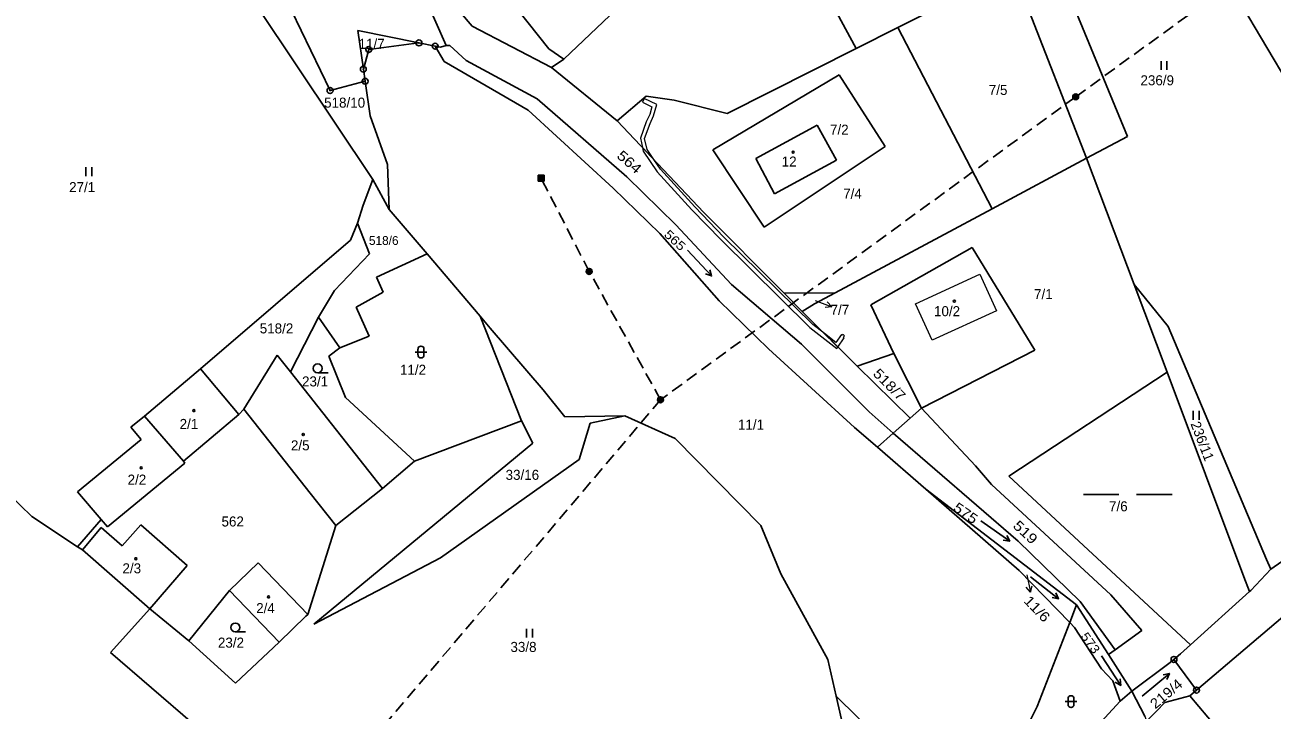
# Model space of a CAD drawing. Extents: x -885985 to -883535, y -1030025 to -1027941.
# Drawn here: x -884740.1 to -884528.7, y -1028559.6 to -1028443.4 of the extents above; entities that cross this region are included whole.
import ezdxf
from ezdxf.enums import TextEntityAlignment as Align

# ---------------------------------------------------------------- set-up
doc = ezdxf.new("R2010")
doc.units = 0
doc.header["$LTSCALE"] = 0.68
doc.linetypes.add('MEDIUM_DASHED', pattern=[4.5, 3, -1.5])
for name, color, linetype, lineweight in [('1', 7, 'Continuous', 25), ('13', 7, 'Continuous', 13), ('3', 7, 'Continuous', 25), ('4', 7, 'Continuous', 13), ('5', 7, 'Continuous', 25), ('6', 7, 'Continuous', 25), ('7', 7, 'Continuous', 13), ('8', 7, 'Continuous', 25)]:
    doc.layers.add(name, color=color, linetype=linetype, lineweight=lineweight)
doc.layers.add('2', color=7, linetype='Continuous')

msp = doc.modelspace()

# ---------------------------------------------------------------- linework, layer by layer
at = {"layer": '1'}
for p, q in [((-884556.32, -1028401.83), (-884531.74, -1028443.62)), ((-884575.21, -1028409.11), (-884553.2, -1028462.33)), ((-884610.56, -1028426.3), (-884599.2, -1028447.46)), ((-884662.42, -1028433.46), (-884651.31, -1028447.47)), ((-884592.12, -1028443.9), (-884572.61, -1028434.07)), ((-884572.61, -1028434.07), (-884560.14, -1028466.04)), ((-884636.88, -1028437.92), (-884648.77, -1028449.22)), ((-884681.12, -1028469.67), (-884700.53, -1028440.64)), ((-884668.71, -1028446.95), (-884672.22, -1028438.93)), ((-884694.93, -1028441.01), (-884688.38, -1028454.57)), ((-884666.24, -1028441.34), (-884664.31, -1028443.64)), ((-884664.31, -1028443.64), (-884650.86, -1028450.66)), ((-884599.2, -1028447.46), (-884592.12, -1028443.9)), ((-884576.15, -1028474.62), (-884592.12, -1028443.9)), ((-884531.74, -1028443.62), (-884517.46, -1028467.79)), ((-884681.82, -1028447.6), (-884673.31, -1028446.49)), ((-884673.31, -1028446.49), (-884670.55, -1028447.05)), ((-884670.55, -1028447.05), (-884669.01, -1028449.65)), ((-884670.55, -1028447.05), (-884669.68, -1028447.22)), ((-884669.68, -1028447.22), (-884668.71, -1028446.95)), ((-884668.71, -1028446.95), (-884668.09, -1028446.91)), ((-884668.09, -1028446.91), (-884665.31, -1028449.46)), ((-884682.73, -1028450.95), (-884681.82, -1028447.6)), ((-884651.31, -1028447.47), (-884648.77, -1028449.22)), ((-884650.86, -1028450.66), (-884648.77, -1028449.22)), ((-884599.2, -1028447.46), (-884621.05, -1028458.46)), ((-884682.44, -1028452.99), (-884682.73, -1028450.95)), ((-884669.01, -1028449.65), (-884654.78, -1028457.91)), ((-884665.31, -1028449.46), (-884653.27, -1028455.95)), ((-884650.86, -1028450.66), (-884639.69, -1028459.71)), ((-884688.38, -1028454.57), (-884682.44, -1028452.99)), ((-884682.44, -1028452.99), (-884681.6, -1028458.88)), ((-884623.49, -1028464.59), (-884602.1, -1028451.92)), ((-884602.1, -1028451.92), (-884594.29, -1028464.04)), ((-884639.69, -1028459.71), (-884634.82, -1028455.53)), ((-884634.82, -1028455.53), (-884630.02, -1028456.22)), ((-884653.27, -1028455.95), (-884638.05, -1028469.2)), ((-884630.02, -1028456.22), (-884621.05, -1028458.46)), ((-884681.6, -1028458.88), (-884678.63, -1028467.13)), ((-884654.78, -1028457.91), (-884640.39, -1028471.1)), ((-884639.69, -1028459.71), (-884625, -1028475.22)), ((-884616.21, -1028466.09), (-884605.79, -1028460.43)), ((-884605.79, -1028460.43), (-884602.55, -1028466.35)), ((-884553.2, -1028462.33), (-884560.14, -1028466.04)), ((-884614.8, -1028477.73), (-884623.49, -1028464.59)), ((-884613.03, -1028472.1), (-884616.21, -1028466.09)), ((-884594.29, -1028464.04), (-884614.8, -1028477.73)), ((-884576.15, -1028474.62), (-884560.14, -1028466.04)), ((-884560.14, -1028466.04), (-884552.09, -1028487.46)), ((-884678.63, -1028467.13), (-884678.35, -1028474.71)), ((-884602.55, -1028466.35), (-884613.03, -1028472.1)), ((-884682.77, -1028474.02), (-884681.12, -1028469.67)), ((-884678.35, -1028474.71), (-884681.12, -1028469.67)), ((-884638.05, -1028469.2), (-884629.79, -1028477.34)), ((-884640.39, -1028471.1), (-884632.48, -1028478.81)), ((-884683.74, -1028477.05), (-884682.77, -1028474.02)), ((-884671.9, -1028482.28), (-884678.35, -1028474.71)), ((-884625, -1028475.22), (-884611.42, -1028488.93)), ((-884602.78, -1028488.87), (-884576.15, -1028474.62)), ((-884684.94, -1028479.93), (-884683.74, -1028477.05)), ((-884683.74, -1028477.05), (-884681.72, -1028482.27)), ((-884632.48, -1028478.81), (-884622.39, -1028490.2)), ((-884629.79, -1028477.34), (-884620.32, -1028487.43)), ((-884710.34, -1028501.74), (-884684.94, -1028479.93)), ((-884681.72, -1028482.27), (-884687.65, -1028488.49)), ((-884680.49, -1028486.21), (-884671.9, -1028482.28)), ((-884662.93, -1028492.81), (-884671.9, -1028482.28)), ((-884596.68, -1028490.88), (-884579.51, -1028481.17)), ((-884579.51, -1028481.17), (-884568.93, -1028498.58)), ((-884679.38, -1028488.73), (-884680.49, -1028486.21)), ((-884687.65, -1028488.49), (-884690.33, -1028492.98)), ((-884683.95, -1028491.32), (-884679.38, -1028488.73)), ((-884620.32, -1028487.43), (-884608.48, -1028497.57)), ((-884611.42, -1028488.93), (-884602.78, -1028488.87)), ((-884611.42, -1028488.93), (-884608.37, -1028492.02)), ((-884606.23, -1028490.72), (-884602.78, -1028488.87)), ((-884546.3, -1028494.59), (-884552.09, -1028487.46)), ((-884546.5, -1028502.34), (-884552.09, -1028487.46)), ((-884681.75, -1028496.21), (-884683.95, -1028491.32)), ((-884622.39, -1028490.2), (-884614.07, -1028498.38)), ((-884608.37, -1028492.02), (-884606.23, -1028490.72)), ((-884592.83, -1028499.15), (-884596.68, -1028490.88)), ((-884690.33, -1028492.98), (-884695.09, -1028502.26)), ((-884690.33, -1028492.98), (-884686.71, -1028498.18)), ((-884608.37, -1028492.02), (-884599.03, -1028501.29)), ((-884773, -1028493.92), (-884738.95, -1028526.77)), ((-884661.22, -1028494.85), (-884652.28, -1028505.29)), ((-884529.63, -1028534.07), (-884546.3, -1028494.59)), ((-884686.71, -1028498.18), (-884681.75, -1028496.21)), ((-884608.48, -1028497.57), (-884597.01, -1028509.07)), ((-884697.32, -1028499.43), (-884703.01, -1028508.61)), ((-884695.09, -1028502.26), (-884697.32, -1028499.43)), ((-884688.6, -1028499.59), (-884686.71, -1028498.18)), ((-884685.76, -1028506.6), (-884688.6, -1028499.59)), ((-884614.07, -1028498.38), (-884599.45, -1028511.68)), ((-884599.03, -1028501.29), (-884592.83, -1028499.15)), ((-884592.83, -1028499.15), (-884588.11, -1028508.4)), ((-884568.93, -1028498.58), (-884588.11, -1028508.4)), ((-884710.34, -1028501.74), (-884719.81, -1028509.75)), ((-884703.83, -1028509.49), (-884710.34, -1028501.74)), ((-884599.03, -1028501.29), (-884590.06, -1028510.09)), ((-884679.5, -1028522.02), (-884695.09, -1028502.26)), ((-884573.29, -1028519.93), (-884546.5, -1028502.34)), ((-884533.47, -1028537), (-884546.5, -1028502.34)), ((-884652.28, -1028505.29), (-884648.6, -1028509.88)), ((-884674.08, -1028517.38), (-884685.76, -1028506.6)), ((-884590.06, -1028510.09), (-884588.11, -1028508.4)), ((-884588.11, -1028508.4), (-884578.97, -1028518.18)), ((-884719.81, -1028509.75), (-884722.14, -1028511.67)), ((-884713.22, -1028517.42), (-884719.81, -1028509.75)), ((-884713.22, -1028517.42), (-884703.83, -1028509.49)), ((-884703.83, -1028509.49), (-884703.01, -1028508.61)), ((-884703.01, -1028508.61), (-884691.74, -1028522.82)), ((-884648.6, -1028509.88), (-884638.43, -1028509.73)), ((-884638.43, -1028509.73), (-884644.27, -1028510.97)), ((-884629.87, -1028513.55), (-884638.43, -1028509.73)), ((-884597.01, -1028509.07), (-884592.91, -1028512.64)), ((-884592.91, -1028512.64), (-884590.06, -1028510.09)), ((-884722.14, -1028511.67), (-884720.38, -1028513.76)), ((-884674.08, -1028517.38), (-884655.95, -1028510.57)), ((-884653.99, -1028514.34), (-884655.95, -1028510.57)), ((-884644.27, -1028510.97), (-884646.15, -1028517.1)), ((-884599.45, -1028511.68), (-884595.59, -1028515.05)), ((-884592.91, -1028512.64), (-884595.59, -1028515.05)), ((-884592.91, -1028512.64), (-884571.73, -1028530.95)), ((-884720.38, -1028513.76), (-884731.22, -1028522.6)), ((-884691.12, -1028545.04), (-884653.99, -1028514.34)), ((-884615.36, -1028528.29), (-884629.87, -1028513.55)), ((-884595.59, -1028515.05), (-884587.41, -1028522.17)), ((-884726.13, -1028528.55), (-884712.97, -1028517.76)), ((-884712.97, -1028517.76), (-884713.22, -1028517.42)), ((-884679.5, -1028522.02), (-884674.08, -1028517.38)), ((-884646.15, -1028517.1), (-884669.65, -1028533.81)), ((-884578.97, -1028518.18), (-884576.28, -1028521.36)), ((-884544.9, -1028546.32), (-884573.29, -1028519.93)), ((-884731.22, -1028522.6), (-884727.19, -1028527.32)), ((-884691.74, -1028522.82), (-884687.39, -1028528.3)), ((-884687.39, -1028528.3), (-884679.5, -1028522.02)), ((-884587.41, -1028522.17), (-884571.59, -1028535.96)), ((-884587.41, -1028522.17), (-884561.86, -1028541.74)), ((-884576.28, -1028521.36), (-884556.05, -1028540.05)), ((-884738.95, -1028526.77), (-884731.18, -1028531.92)), ((-884727.19, -1028527.32), (-884731.18, -1028531.92)), ((-884727.19, -1028527.32), (-884726.13, -1028528.55)), ((-884727.2, -1028528.67), (-884730.37, -1028532.45)), ((-884723.61, -1028531.77), (-884727.2, -1028528.67)), ((-884720.48, -1028528.2), (-884723.61, -1028531.77)), ((-884712.6, -1028535.1), (-884720.48, -1028528.2)), ((-884692.17, -1028543.38), (-884687.39, -1028528.3)), ((-884611.99, -1028536.52), (-884615.36, -1028528.29)), ((-884571.73, -1028530.95), (-884561.2, -1028541.18)), ((-884528.9, -1028535.72), (-884521.21, -1028530.3)), ((-884731.18, -1028531.92), (-884730.37, -1028532.45)), ((-884730.37, -1028532.45), (-884718.91, -1028542.44)), ((-884712.6, -1028535.1), (-884718.91, -1028542.44)), ((-884700.56, -1028534.64), (-884705.42, -1028539.35)), ((-884692.17, -1028543.38), (-884700.56, -1028534.64)), ((-884669.65, -1028533.81), (-884691.12, -1028545.04)), ((-884532.3, -1028539.31), (-884528.9, -1028535.72)), ((-884528.9, -1028535.72), (-884529.63, -1028534.07)), ((-884603.97, -1028551.04), (-884611.99, -1028536.52)), ((-884571.59, -1028535.96), (-884562.97, -1028544.77)), ((-884532.53, -1028539.51), (-884533.47, -1028537)), ((-884705.42, -1028539.35), (-884712.34, -1028547.85)), ((-884697.02, -1028548.08), (-884705.42, -1028539.35)), ((-884556.05, -1028540.05), (-884550.74, -1028546.11)), ((-884542.49, -1028548.55), (-884532.53, -1028539.51)), ((-884541.49, -1028556.22), (-884520.3, -1028538.19)), ((-884532.53, -1028539.51), (-884532.3, -1028539.31)), ((-884561.86, -1028541.74), (-884562.97, -1028544.77)), ((-884561.86, -1028541.74), (-884556.4, -1028550.2)), ((-884561.2, -1028541.18), (-884555.27, -1028549.38)), ((-884718.91, -1028542.44), (-884725.57, -1028549.84)), ((-884718.91, -1028542.44), (-884712.34, -1028547.85)), ((-884697.02, -1028548.08), (-884692.49, -1028543.71)), ((-884692.49, -1028543.71), (-884692.17, -1028543.38)), ((-884562.97, -1028544.77), (-884568.51, -1028559.01)), ((-884562.16, -1028545.6), (-884562.97, -1028544.77)), ((-884557.59, -1028552.6), (-884562.16, -1028545.6)), ((-884550.74, -1028546.11), (-884555.27, -1028549.38)), ((-884542.49, -1028548.55), (-884544.9, -1028546.32)), ((-884712.34, -1028547.85), (-884704.39, -1028555.06)), ((-884704.39, -1028555.06), (-884697.02, -1028548.08)), ((-884543.64, -1028549.59), (-884542.49, -1028548.55)), ((-884725.57, -1028549.84), (-884711.72, -1028561.82)), ((-884555.27, -1028549.38), (-884556.4, -1028550.2)), ((-884556.4, -1028550.2), (-884552.45, -1028556.38)), ((-884545.32, -1028551.02), (-884544.23, -1028550.09)), ((-884544.23, -1028550.09), (-884543.64, -1028549.59)), ((-884602.56, -1028557.23), (-884603.97, -1028551.04)), ((-884555.69, -1028554.68), (-884557.59, -1028552.6)), ((-884552.45, -1028556.38), (-884545.96, -1028551.56)), ((-884545.96, -1028551.56), (-884545.32, -1028551.02)), ((-884545.32, -1028551.02), (-884541.49, -1028556.22)), ((-884554.43, -1028558.08), (-884555.69, -1028554.68)), ((-884552.45, -1028556.38), (-884554.43, -1028558.08)), ((-884550.25, -1028560.62), (-884552.45, -1028556.38)), ((-884542.63, -1028557.19), (-884541.49, -1028556.22)), ((-884602.56, -1028557.23), (-884579.05, -1028580.4)), ((-884600.83, -1028564.87), (-884602.56, -1028557.23)), ((-884568.51, -1028559.01), (-884576.14, -1028574.34)), ((-884554.43, -1028558.08), (-884568.33, -1028573.09)), ((-884546.85, -1028558.35), (-884548.28, -1028559.79)), ((-884542.63, -1028557.19), (-884546.85, -1028558.35)), ((-884542.63, -1028557.19), (-884530.79, -1028571.17))]:
    msp.add_line(p, q, dxfattribs=at)
for points in [[(-884682.73, -1028450.95), (-884683.67, -1028444.39), (-884673.31, -1028446.49)], [(-884655.95, -1028510.57), (-884662.93, -1028492.81), (-884661.22, -1028494.85)]]:
    msp.add_lwpolyline(points, dxfattribs=at)
at = {"layer": '13'}
for points in [[(-884633.47, -1028466.28), (-884634.64, -1028464.55), (-884635.05, -1028462.67), (-884634.13, -1028460.13), (-884633.53, -1028458.85), (-884633.01, -1028456.93), (-884635.12, -1028455.89), (-884635.43, -1028456.52), (-884633.83, -1028457.31), (-884634.19, -1028458.61), (-884634.77, -1028459.87), (-884635.77, -1028462.63), (-884635.43, -1028464.2)], [(-884602.28, -1028498.07), (-884604.58, -1028495.78), (-884606.56, -1028494.24), (-884621.6, -1028479.4), (-884626.52, -1028474.31), (-884632.36, -1028467.9), (-884633.47, -1028466.28), (-884635.43, -1028464.2), (-884635.3, -1028464.83), (-884632.91, -1028468.34), (-884627.04, -1028474.79), (-884622.1, -1028479.88), (-884607.02, -1028494.76), (-884602.46, -1028498.33)], [(-884601.68, -1028495.95), (-884602.62, -1028497.31), (-884604.58, -1028495.78), (-884602.28, -1028498.07), (-884601.2, -1028496.47), (-884601.35, -1028496.31), (-884601.17, -1028496.15), (-884601.39, -1028495.91), (-884601.57, -1028496.07)], [(-884546.85, -1028558.35), (-884542.63, -1028557.19), (-884541.49, -1028556.22), (-884545.32, -1028551.02), (-884545.96, -1028551.56), (-884552.45, -1028556.38), (-884550.25, -1028560.62), (-884549.96, -1028561.5), (-884548.28, -1028559.79)]]:
    msp.add_lwpolyline(points, close=True, dxfattribs=at)
at = {"layer": '3'}
for p, q in [((-884547.511, -1028451.06), (-884547.511, -1028449.56)), ((-884546.51, -1028451.06), (-884546.51, -1028449.56)), ((-884729.761, -1028469.07), (-884729.761, -1028467.57)), ((-884728.76, -1028469.07), (-884728.76, -1028467.57)), ((-884623.709, -1028486.002), (-884624.742, -1028485.63)), ((-884673.971, -1028498.901), (-884671.969, -1028498.901)), ((-884673.471, -1028498.401), (-884673.471, -1028499.402)), ((-884672.469, -1028499.402), (-884672.469, -1028498.401)), ((-884690.473, -1028502.42), (-884688.723, -1028502.42)), ((-884542.071, -1028510.38), (-884542.071, -1028508.88)), ((-884541.07, -1028510.38), (-884541.07, -1028508.88)), ((-884560.649, -1028523.06), (-884554.649, -1028523.06)), ((-884551.649, -1028523.06), (-884545.649, -1028523.06)), ((-884573.163, -1028530.958), (-884574.251, -1028530.808)), ((-884564.898, -1028540.734), (-884565.976, -1028540.528)), ((-884704.443, -1028546.35), (-884702.693, -1028546.35)), ((-884655.061, -1028547.32), (-884655.061, -1028545.82)), ((-884654.06, -1028547.32), (-884654.06, -1028545.82)), ((-884554.334, -1028555.425), (-884555.287, -1028554.879)), ((-884546.093, -1028553.417), (-884546.519, -1028554.429)), ((-884563.771, -1028558.181), (-884561.769, -1028558.181)), ((-884563.271, -1028557.681), (-884563.271, -1028558.682)), ((-884562.269, -1028558.682), (-884562.269, -1028557.681))]:
    msp.add_line(p, q, dxfattribs=at)
for points in [[(-884627.801, -1028481.614), (-884623.709, -1028486.002), (-884624.008, -1028484.946)], [(-884578.078, -1028527.516), (-884573.163, -1028530.958), (-884573.676, -1028529.986)], [(-884569.626, -1028537.04), (-884564.898, -1028540.734), (-884565.359, -1028539.738)], [(-884557.602, -1028550.393), (-884554.334, -1028555.425), (-884554.446, -1028554.332)], [(-884550.689, -1028557.274), (-884546.093, -1028553.417), (-884547.164, -1028553.661)]]:
    msp.add_lwpolyline(points, dxfattribs=at)
for centre in [(-884690.4729, -1028501.6698), (-884704.4429, -1028545.5998)]:
    msp.add_circle(centre, 0.75, dxfattribs=at)
for centre, start, end in [((-884672.97, -1028498.4009), 0, 180), ((-884672.97, -1028499.4009), 180, 359.98789), ((-884562.77, -1028557.6809), 0, 180), ((-884562.77, -1028558.6809), 180, 359.98789)]:
    msp.add_arc(centre, 0.5, start, end, dxfattribs=at)
at = {"layer": '4'}
for p, q in [((-884589.14, -1028490.75), (-884578.22, -1028485.72)), ((-884578.22, -1028485.72), (-884575.42, -1028491.89)), ((-884586.3, -1028496.9), (-884589.14, -1028490.75)), ((-884575.42, -1028491.89), (-884586.3, -1028496.9))]:
    msp.add_line(p, q, dxfattribs=at)
at = {"layer": '5'}
for centre in [(-884609.8868, -1028465.0092), (-884582.5468, -1028490.2892), (-884711.4568, -1028508.8392), (-884692.9168, -1028512.8892), (-884720.4068, -1028518.5392), (-884721.3068, -1028533.9492), (-884698.7968, -1028540.4292)]:
    msp.add_circle(centre, 0.175, dxfattribs=at)
at = {"layer": '6', "linetype": 'MEDIUM_DASHED'}
for p, q in [((-884498.42, -1028409.47), (-884561.98, -1028455.63)), ((-884561.98, -1028455.63), (-884632.35, -1028506.99)), ((-884644.44, -1028485.23), (-884652.61, -1028469.44)), ((-884632.35, -1028506.99), (-884644.44, -1028485.23)), ((-884632.35, -1028506.99), (-884685.55, -1028569.69))]:
    msp.add_line(p, q, dxfattribs=at)
at = {"layer": '6'}
for p, q in [((-884653.112, -1028468.939), (-884652.111, -1028468.939)), ((-884653.112, -1028469.939), (-884653.112, -1028468.939)), ((-884653.112, -1028469.139), (-884652.111, -1028469.139)), ((-884653.112, -1028469.339), (-884652.111, -1028469.339)), ((-884653.112, -1028469.539), (-884652.111, -1028469.539)), ((-884653.112, -1028469.739), (-884652.111, -1028469.739)), ((-884653.112, -1028469.939), (-884652.111, -1028469.939)), ((-884652.911, -1028469.939), (-884652.911, -1028468.939)), ((-884652.712, -1028469.939), (-884652.712, -1028468.939)), ((-884652.511, -1028469.939), (-884652.511, -1028468.939)), ((-884652.312, -1028469.939), (-884652.312, -1028468.939)), ((-884652.111, -1028469.939), (-884652.111, -1028468.939))]:
    msp.add_line(p, q, dxfattribs=at)
for centre, radius in [((-884561.9834, -1028455.6299), 0.5), ((-884561.9834, -1028455.6299), 0.4), ((-884561.9834, -1028455.6299), 0.3), ((-884561.9834, -1028455.6299), 0.2), ((-884561.9834, -1028455.6299), 0.1), ((-884644.4434, -1028485.2299), 0.5), ((-884644.4434, -1028485.2299), 0.4), ((-884644.4434, -1028485.2299), 0.3), ((-884644.4434, -1028485.2299), 0.2), ((-884644.4434, -1028485.2299), 0.1), ((-884632.3534, -1028506.9899), 0.5), ((-884632.3534, -1028506.9899), 0.4), ((-884632.3534, -1028506.9899), 0.3), ((-884632.3534, -1028506.9899), 0.2), ((-884632.3534, -1028506.9899), 0.1)]:
    msp.add_circle(centre, radius, dxfattribs=at)
at = {"layer": '7'}
for p, q in [((-884603.34, -1028491.216), (-884604.11, -1028490.403)), ((-884569.666, -1028539.635), (-884569.384, -1028538.552))]:
    msp.add_line(p, q, dxfattribs=at)
for points in [[(-884606.16, -1028490.19), (-884603.34, -1028491.216), (-884604.452, -1028491.344)], [(-884570.29, -1028536.7), (-884569.666, -1028539.635), (-884570.364, -1028538.76)]]:
    msp.add_lwpolyline(points, dxfattribs=at)
at = {"layer": '8'}
for centre, radius in [((-884681.82, -1028447.5999), 0.5), ((-884673.31, -1028446.4899), 0.5), ((-884673.31, -1028446.4899), 0.0303), ((-884670.55, -1028447.0499), 0.5), ((-884670.55, -1028447.0499), 0.0303), ((-884681.82, -1028447.5999), 0.0303), ((-884682.73, -1028450.9499), 0.5), ((-884682.73, -1028450.9499), 0.0303), ((-884682.44, -1028452.9899), 0.5), ((-884682.44, -1028452.9899), 0.0303), ((-884688.38, -1028454.5699), 0.5), ((-884688.38, -1028454.5699), 0.0303), ((-884545.32, -1028551.0199), 0.5), ((-884545.32, -1028551.0199), 0.0303), ((-884541.49, -1028556.2199), 0.5), ((-884541.49, -1028556.2199), 0.0303)]:
    msp.add_circle(centre, radius, dxfattribs=at)

# ---------------------------------------------------------------- texts
at = {"layer": '2'}
for s, p in [('11/7', (-884681.339, -1028447.495)), ('518/10', (-884685.91, -1028457.465)), ('7/7', (-884601.95, -1028492.585))]:
    msp.add_text(s, height=1.7, dxfattribs=at).set_placement(p, align=Align.CENTER)
for s, height, p in [('236/9', 1.7, (-884551, -1028453.675)), ('7/5', 1.7, (-884576.71, -1028455.315)), ('7/2', 1.7, (-884603.63, -1028462.045)), ('12', 1.7, (-884611.82, -1028467.455)), ('27/1', 1.7, (-884732.61, -1028471.785)), ('7/4', 1.7, (-884601.4, -1028472.915)), ('518/6', 1.5, (-884681.79, -1028480.745)), ('7/1', 1.7, (-884569.04, -1028489.935)), ('10/2', 1.7, (-884586, -1028492.825)), ('518/2', 1.7, (-884700.3, -1028495.745)), ('11/2', 1.7, (-884676.53, -1028502.765)), ('23/1', 1.7, (-884693.13, -1028504.735)), ('2/1', 1.7, (-884713.88, -1028511.945)), ('11/1', 1.7, (-884619.23, -1028512.055)), ('2/5', 1.7, (-884695.01, -1028515.575)), ('33/16', 1.7, (-884658.62, -1028520.575)), ('2/2', 1.7, (-884722.7, -1028521.385)), ('7/6', 1.7, (-884556.33, -1028525.915)), ('562', 1.7, (-884706.78, -1028528.485)), ('2/3', 1.7, (-884723.57, -1028536.425)), ('2/4', 1.7, (-884700.9, -1028543.175)), ('23/2', 1.7, (-884707.39, -1028549.025)), ('33/8', 1.7, (-884657.8, -1028549.755))]:
    msp.add_text(s, height=height, dxfattribs=at).set_placement(p)
for s, height, rotation, width, p in [('564', 1.7, 319, 1.2, (-884639.918, -1028465.83)), ('565', 1.5, 317, 1.2, (-884631.885, -1028479.134)), ('518/7', 1.7, 315, 1.15, (-884596.47, -1028502.71)), ('575', 1.7, 325, 1.15, (-884582.903, -1028525.668)), ('519', 1.7, 317, 1.2, (-884572.749, -1028528.53)), ('573', 1.5, 306, 1.15, (-884561.223, -1028547.12))]:
    msp.add_text(s, height=height, rotation=rotation, dxfattribs=dict(at, width=width)).set_placement(p)
msp.add_text('236/11', height=1.7, rotation=291, dxfattribs=at).set_placement((-884542.546, -1028511.072))
for s, rotation, width, p in [('11/6', 314, 1.15, (-884569.1442, -1028543.0355)), ('219/4', 40, 1.1, (-884546.0884, -1028557.5017))]:
    msp.add_text(s, height=1.7, rotation=rotation, dxfattribs=dict(at, width=width)).set_placement(p, align=Align.CENTER)

doc.saveas('drawing.dxf')
